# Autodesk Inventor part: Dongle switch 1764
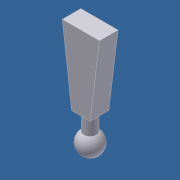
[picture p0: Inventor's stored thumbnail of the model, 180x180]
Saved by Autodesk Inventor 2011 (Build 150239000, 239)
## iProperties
Created: 2010-01
Part Number: Dongle switch 1764
Document SubType Name: Modeling
Designer: jgehrig
Density: 1 g/cm^3
Author: jgehrig
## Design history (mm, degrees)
sketch "Sketch1"
  geometry: L1 (-6.921, 27.03)-(-1.841, 27.03); L2 (-3.111, 16.87)-(-5.651, 16.87); L3 (-6.921, 27.03)-(-5.651, 16.87); L4 (-3.111, 16.87)-(-1.841, 27.03); 1 further point
  constraints: 8 end point, 1 horizontal, 1 parallel
  dimensions: "d0" = 5.08 distance of L1.start L1.end; "d1" = 2.54 distance of L2.start L2.end; "d2" = 10.16 distance between parallel lines of L2 L1; "d3" = 1.27 horizontal distance of L1.start L2.end
extrude "Extrusion1" new body sketch "Sketch1" distance "d4" = 2.54; taper "d5" = 0 deg
workplane "Work Plane1"
sketch "Sketch2"
  geometry: L1 (-3.111, 16.87)-(-5.651, 16.87) reference; L2 (-4.381, 16.87)-(-4.381, 14.33); L3 (-3.492, 16.87)-(-3.492, 14.33); L4 (-4.381, 14.33)-(-3.492, 14.33); L5 (-4.381, 16.87)-(-3.492, 16.87); L6 (-4.381, 14.33)-(-4.381, 11.536); L7 (-4.381, 16.87)-(-3.492, 16.87); L8 (-3.492, 16.87)-(-4.381, 16.87); L9 (-4.381, 16.87)-(-3.492, 16.87); L10 (-3.492, 16.87)-(-3.492, 14.33); L11 (-3.492, 14.33)-(-4.381, 14.33); L12 (-4.381, 14.33)-(-4.381, 16.87); A1 r 1.587 centre (-4.381, 13.124) between (-4.381, 11.536) and (-4.381, 14.711); 1 further point
  constraints: 22 end point, 5 perpendicular, 3 parallel, 2 collinear, 2 point on circle, 2 point on line, 1 centre point, 1 horizontal, 1 midpoint
  dimensions: "d7" = 2.54 distance of L2.start L2.end; "d8" = 0.889 distance of L2.end L3.end; "d9" = 0 distance from line of L6 A1.centre; "d10" = 0.381 distance of A1.end L2.end; "d11" = 3.175 distance of L6.end A1.end
revolve "Revolution1" sketch "Sketch2" stored, may be unused: angle "d12" = 90 deg
body "Solid1"
other parameters: "d6" = 1.27
